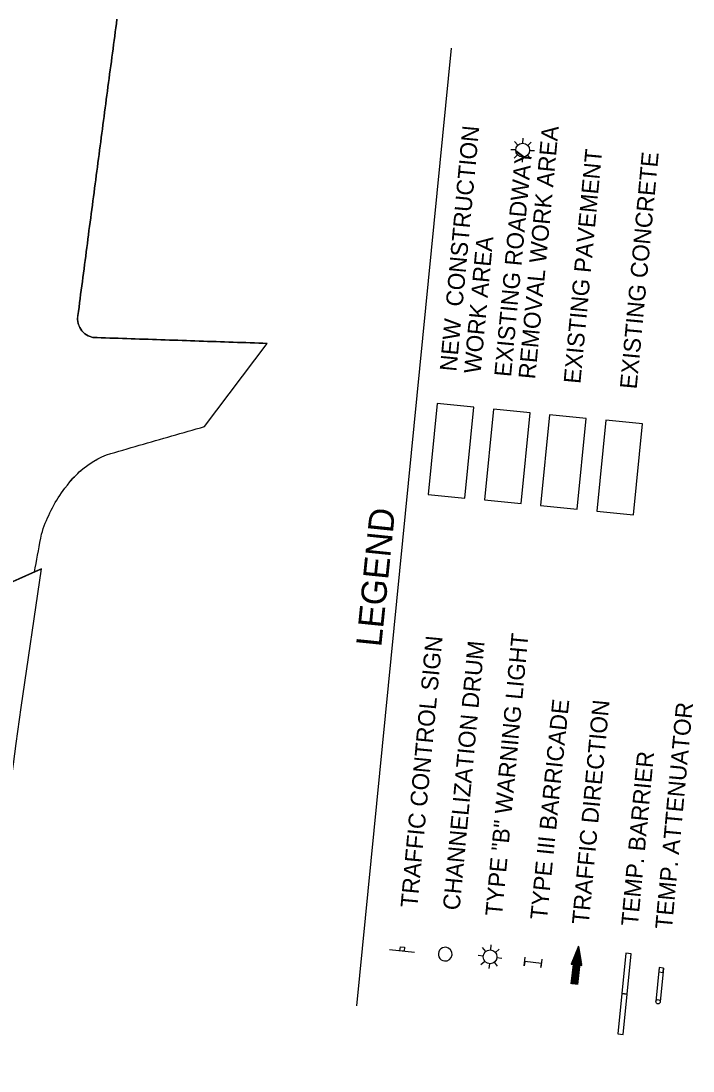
# Model space of a CAD drawing. Extents: x 1795987 to 1799700, y 243690 to 251545.
# Drawn here: x 1797662.2 to 1797973.5, y 245413.3 to 245899.5 of the extents above; entities that cross this region are included whole.
import ezdxf

# ---------------------------------------------------------------- set-up
doc = ezdxf.new("R2010")
doc.units = 0
for name, color, linetype in [('Level 23', 7, 'Continuous'), ('Level 31', 7, 'Continuous'), ('Level 4', 7, 'Continuous'), ('Prop_Horiz Alignment', 7, 'Continuous')]:
    doc.layers.add(name, color=color, linetype=linetype)

# ---------------------------------------------------------------- blocks, each defined once
blk = doc.blocks.new('T21LR')
at = {"layer": 'Level 23'}
for p, q in [((0, 2), (31.5, 2)), ((0, -2), (31.5, -2))]:
    blk.add_line(p, q, dxfattribs=at)
blk.add_lwpolyline([(0, -2), (4, -2), (4, 2), (0, 2)], close=True, dxfattribs=at)
blk.add_circle((31.5, 0), 2, dxfattribs=at)

msp = doc.modelspace()

# ---------------------------------------------------------------- linework, layer by layer
at = {"layer": 'Level 31'}
for p, q in [((1797817.74, 245443.45), (1797861.68, 245886.96)), ((1797877.46, 245468.63), (1797875.99, 245470.41)), ((1797879.8, 245469.34), (1797880.02, 245471.64)), ((1797920.43, 245471.1), (1797916.98, 245462.78)), ((1797921.95, 245462.22), (1797920.43, 245471.1)), ((1797844.52, 245468.23), (1797832.88, 245469.38)), ((1797876.3, 245466.47), (1797874, 245466.7)), ((1797883.74, 245469.65), (1797881.95, 245468.18)), ((1797882.66, 245465.84), (1797884.96, 245465.61)), ((1797875.22, 245462.67), (1797877.01, 245464.13)), ((1797879.17, 245462.98), (1797878.94, 245460.68)), ((1797882.97, 245461.9), (1797881.51, 245463.69)), ((1797917.92, 245462.67), (1797916.9, 245453.65)), ((1797916.98, 245462.78), (1797917.92, 245462.67)), ((1797920, 245453.3), (1797921.02, 245462.33)), ((1797921.02, 245462.33), (1797921.95, 245462.22))]:
    msp.add_line(p, q, dxfattribs=at)
for points in [[(1797867.8, 245678.59), (1797871.97, 245720.66), (1797854.98, 245722.34), (1797850.81, 245680.28)], [(1797893.84, 245676.01), (1797898, 245718.08), (1797881.02, 245719.76), (1797876.85, 245677.7)], [(1797919.87, 245673.43), (1797924.04, 245715.5), (1797907.05, 245717.18), (1797902.88, 245675.12)], [(1797945.91, 245670.85), (1797950.08, 245712.92), (1797933.09, 245714.61), (1797928.92, 245672.54)], [(1797837.73, 245468.9), (1797837.92, 245470.84), (1797839.86, 245470.65), (1797839.67, 245468.71)], [(1797944.86, 245467.59), (1797942.37, 245467.84), (1797940.52, 245449.18), (1797943.01, 245448.93)], [(1797943.01, 245448.93), (1797940.52, 245449.18), (1797938.68, 245430.52), (1797941.17, 245430.27)]]:
    msp.add_lwpolyline(points, close=True, dxfattribs=at)
for points in [[(1797920.3, 245470.77), (1797918.36, 245453.49)], [(1797920.53, 245470.52), (1797918.61, 245453.46)], [(1797903.5, 245465.04), (1797903.05, 245461.16), (1797903.28, 245463.1), (1797895.53, 245464), (1797895.3, 245462.06), (1797895.75, 245465.94)], [(1797918.5, 245466.45), (1797917.06, 245453.63)], [(1797918.86, 245467.32), (1797917.32, 245453.6)], [(1797919.22, 245468.18), (1797917.58, 245453.57)], [(1797918.15, 245465.59), (1797917.82, 245462.68)], [(1797919.58, 245469.05), (1797917.84, 245453.54)], [(1797919.94, 245469.91), (1797918.1, 245453.51)], [(1797920.69, 245469.6), (1797918.87, 245453.43)], [(1797920.85, 245468.68), (1797919.13, 245453.4)], [(1797921.01, 245467.75), (1797919.39, 245453.37)], [(1797921.16, 245466.83), (1797919.65, 245453.34)], [(1797921.32, 245465.91), (1797919.91, 245453.31)], [(1797917.07, 245463), (1797917.04, 245462.77)], [(1797917.43, 245463.86), (1797917.3, 245462.74)], [(1797917.79, 245464.72), (1797917.56, 245462.71)], [(1797921.48, 245464.99), (1797921.18, 245462.31)], [(1797921.64, 245464.06), (1797921.44, 245462.28)], [(1797921.8, 245463.14), (1797921.7, 245462.25)]]:
    msp.add_lwpolyline(points, dxfattribs=at)
msp.add_circle((1797879.48, 245466.16), 3.19, dxfattribs=at)
for start, end in [(84.3414, 264.3414), (264.3414, 84.3414)]:
    msp.add_arc((1797858.72, 245467.4), 3.18, start, end, dxfattribs=at)
at = {"layer": 'Level 4'}
for p, q in [((1797894.68, 245842.86), (1797894.75, 245845.17)), ((1797891.39, 245839.77), (1797889.08, 245839.84)), ((1797892.39, 245842), (1797890.81, 245843.68)), ((1797898.59, 245843.44), (1797896.91, 245841.86)), ((1797890.57, 245835.9), (1797892.25, 245837.48)), ((1797894.48, 245836.48), (1797894.41, 245834.17)), ((1797898.35, 245835.66), (1797896.77, 245837.34)), ((1797897.77, 245839.57), (1797900.08, 245839.5))]:
    msp.add_line(p, q, dxfattribs=at)
msp.add_circle((1797894.58, 245839.67), 3.19, dxfattribs=at)
at = {"layer": 'Prop_Horiz Alignment'}
for p, q in [((1797706.15, 245896.39), (1797706.41, 245898.35)), ((1797706.41, 245898.35), (1797706.67, 245900.31)), ((1797705.62, 245892.48), (1797705.88, 245894.44)), ((1797705.88, 245894.44), (1797706.15, 245896.39)), ((1797704.84, 245886.62), (1797705.1, 245888.57)), ((1797705.1, 245888.57), (1797705.36, 245890.53)), ((1797705.36, 245890.53), (1797705.62, 245892.48)), ((1797704.32, 245882.71), (1797704.58, 245884.66)), ((1797704.58, 245884.66), (1797704.84, 245886.62)), ((1797703.54, 245876.84), (1797703.8, 245878.8)), ((1797703.8, 245878.8), (1797704.06, 245880.75)), ((1797704.06, 245880.75), (1797704.32, 245882.71)), ((1797703.02, 245872.93), (1797703.28, 245874.88)), ((1797703.28, 245874.88), (1797703.54, 245876.84)), ((1797702.25, 245867.06), (1797702.5, 245869.02)), ((1797702.5, 245869.02), (1797702.76, 245870.97)), ((1797702.76, 245870.97), (1797703.02, 245872.93)), ((1797701.73, 245863.15), (1797701.99, 245865.11)), ((1797701.99, 245865.11), (1797702.25, 245867.06)), ((1797700.95, 245857.28), (1797701.21, 245859.24)), ((1797701.21, 245859.24), (1797701.47, 245861.19)), ((1797701.47, 245861.19), (1797701.73, 245863.15)), ((1797700.43, 245853.37), (1797700.69, 245855.33)), ((1797700.69, 245855.33), (1797700.95, 245857.28)), ((1797699.65, 245847.51), (1797699.91, 245849.46)), ((1797699.91, 245849.46), (1797700.17, 245851.42)), ((1797700.17, 245851.42), (1797700.43, 245853.37)), ((1797699.14, 245843.59), (1797699.4, 245845.55)), ((1797699.4, 245845.55), (1797699.65, 245847.51)), ((1797698.36, 245837.73), (1797698.62, 245839.68)), ((1797698.62, 245839.68), (1797698.88, 245841.64)), ((1797698.88, 245841.64), (1797699.14, 245843.59)), ((1797697.84, 245833.82), (1797698.1, 245835.77)), ((1797698.1, 245835.77), (1797698.36, 245837.73)), ((1797697.32, 245829.9), (1797697.58, 245831.86)), ((1797697.58, 245831.86), (1797697.84, 245833.82)), ((1797696.55, 245824.04), (1797696.8, 245825.99)), ((1797696.8, 245825.99), (1797697.06, 245827.95)), ((1797697.06, 245827.95), (1797697.32, 245829.9)), ((1797696.03, 245820.1), (1797696.29, 245822.07)), ((1797696.29, 245822.07), (1797696.55, 245824.04)), ((1797695.26, 245814.21), (1797695.52, 245816.17)), ((1797695.52, 245816.17), (1797695.77, 245818.14)), ((1797695.77, 245818.14), (1797696.03, 245820.1)), ((1797694.74, 245810.27), (1797695, 245812.24)), ((1797695, 245812.24), (1797695.26, 245814.21)), ((1797693.97, 245804.38), (1797694.23, 245806.34)), ((1797694.23, 245806.34), (1797694.49, 245808.31)), ((1797694.49, 245808.31), (1797694.74, 245810.27)), ((1797693.46, 245800.44), (1797693.71, 245802.41)), ((1797693.71, 245802.41), (1797693.97, 245804.38)), ((1797692.69, 245794.55), (1797692.94, 245796.51)), ((1797692.94, 245796.51), (1797693.2, 245798.48)), ((1797693.2, 245798.48), (1797693.46, 245800.44)), ((1797692.17, 245790.61), (1797692.43, 245792.58)), ((1797692.43, 245792.58), (1797692.69, 245794.55)), ((1797691.4, 245784.71), (1797691.66, 245786.68)), ((1797691.66, 245786.68), (1797691.91, 245788.65)), ((1797691.91, 245788.65), (1797692.17, 245790.61)), ((1797690.88, 245780.78), (1797691.14, 245782.75)), ((1797691.14, 245782.75), (1797691.4, 245784.71)), ((1797690.11, 245774.88), (1797690.37, 245776.85)), ((1797690.37, 245776.85), (1797690.63, 245778.82)), ((1797690.63, 245778.82), (1797690.88, 245780.78)), ((1797689.6, 245770.95), (1797689.85, 245772.92)), ((1797689.85, 245772.92), (1797690.11, 245774.88)), ((1797688.83, 245765.05), (1797689.08, 245767.02)), ((1797689.08, 245767.02), (1797689.34, 245768.99)), ((1797689.34, 245768.99), (1797689.6, 245770.95)), ((1797688.45, 245761.22), (1797688.57, 245763.09)), ((1797688.57, 245763.09), (1797688.83, 245765.05)), ((1797688.73, 245759.36), (1797688.45, 245761.22)), ((1797689.39, 245757.61), (1797688.73, 245759.36)), ((1797690.41, 245756.04), (1797689.39, 245757.61)), ((1797691.74, 245754.71), (1797690.41, 245756.04)), ((1797693.32, 245753.7), (1797691.74, 245754.71)), ((1797695.47, 245752.96), (1797693.32, 245753.7)), ((1797697.44, 245752.89), (1797695.47, 245752.96)), ((1797699.41, 245752.82), (1797697.44, 245752.89)), ((1797701.38, 245752.76), (1797699.41, 245752.82)), ((1797703.35, 245752.69), (1797701.38, 245752.76)), ((1797705.32, 245752.62), (1797703.35, 245752.69)), ((1797707.29, 245752.56), (1797705.32, 245752.62)), ((1797709.26, 245752.49), (1797707.29, 245752.56)), ((1797711.23, 245752.42), (1797709.26, 245752.49)), ((1797713.2, 245752.36), (1797711.23, 245752.42)), ((1797715.17, 245752.29), (1797713.2, 245752.36)), ((1797717.14, 245752.22), (1797715.17, 245752.29)), ((1797719.11, 245752.16), (1797717.14, 245752.22)), ((1797721.08, 245752.09), (1797719.11, 245752.16)), ((1797723.05, 245752.02), (1797721.08, 245752.09)), ((1797725.02, 245751.96), (1797723.05, 245752.02)), ((1797726.99, 245751.89), (1797725.02, 245751.96)), ((1797728.96, 245751.82), (1797726.99, 245751.89)), ((1797730.94, 245751.76), (1797728.96, 245751.82)), ((1797732.91, 245751.69), (1797730.94, 245751.76)), ((1797734.88, 245751.63), (1797732.91, 245751.69)), ((1797736.85, 245751.56), (1797734.88, 245751.63)), ((1797738.82, 245751.49), (1797736.85, 245751.56)), ((1797740.79, 245751.43), (1797738.82, 245751.49)), ((1797742.76, 245751.36), (1797740.79, 245751.43)), ((1797744.73, 245751.29), (1797742.76, 245751.36)), ((1797746.7, 245751.23), (1797744.73, 245751.29)), ((1797748.67, 245751.16), (1797746.7, 245751.23)), ((1797747.18, 245711.68), (1797776.25, 245750.23)), ((1797747.18, 245711.68), (1797776.25, 245750.23)), ((1797750.64, 245751.09), (1797748.67, 245751.16)), ((1797752.61, 245751.03), (1797750.64, 245751.09)), ((1797754.58, 245750.96), (1797752.61, 245751.03)), ((1797756.55, 245750.89), (1797754.58, 245750.96)), ((1797758.52, 245750.83), (1797756.55, 245750.89)), ((1797760.49, 245750.76), (1797758.52, 245750.83)), ((1797762.46, 245750.69), (1797760.49, 245750.76)), ((1797764.43, 245750.63), (1797762.46, 245750.69)), ((1797766.4, 245750.56), (1797764.43, 245750.63)), ((1797768.37, 245750.49), (1797766.4, 245750.56)), ((1797770.34, 245750.43), (1797768.37, 245750.49)), ((1797772.31, 245750.36), (1797770.34, 245750.43)), ((1797774.28, 245750.29), (1797772.31, 245750.36)), ((1797776.25, 245750.23), (1797774.28, 245750.29)), ((1797733.97, 245707.89), (1797735.86, 245708.43)), ((1797735.86, 245708.43), (1797737.75, 245708.97)), ((1797737.75, 245708.97), (1797739.63, 245709.52)), ((1797739.63, 245709.52), (1797741.52, 245710.06)), ((1797741.52, 245710.06), (1797743.41, 245710.6)), ((1797743.41, 245710.6), (1797745.3, 245711.14)), ((1797745.3, 245711.14), (1797747.18, 245711.68)), ((1797716.99, 245703.01), (1797718.88, 245703.55)), ((1797718.88, 245703.55), (1797720.76, 245704.1)), ((1797720.76, 245704.1), (1797722.65, 245704.64)), ((1797722.65, 245704.64), (1797724.54, 245705.18)), ((1797724.54, 245705.18), (1797726.43, 245705.72)), ((1797726.43, 245705.72), (1797728.31, 245706.26)), ((1797728.31, 245706.26), (1797730.2, 245706.81)), ((1797730.2, 245706.81), (1797732.09, 245707.35)), ((1797732.09, 245707.35), (1797733.97, 245707.89)), ((1797700.77, 245698.18), (1797701.89, 245698.68)), ((1797701.89, 245698.68), (1797703.78, 245699.22)), ((1797703.78, 245699.22), (1797705.67, 245699.76)), ((1797705.67, 245699.76), (1797707.56, 245700.3)), ((1797707.56, 245700.3), (1797709.44, 245700.84)), ((1797709.44, 245700.84), (1797711.33, 245701.39)), ((1797711.33, 245701.39), (1797713.22, 245701.93)), ((1797713.22, 245701.93), (1797715.1, 245702.47)), ((1797715.1, 245702.47), (1797716.99, 245703.01)), ((1797692.48, 245693.34), (1797694.19, 245694.55)), ((1797694.19, 245694.55), (1797695.96, 245695.68)), ((1797695.96, 245695.68), (1797697.79, 245696.72)), ((1797697.79, 245696.72), (1797699.66, 245697.68)), ((1797699.66, 245697.68), (1797700.77, 245698.18)), ((1797686.25, 245687.73), (1797687.71, 245689.24)), ((1797687.71, 245689.24), (1797689.23, 245690.68)), ((1797689.23, 245690.68), (1797690.82, 245692.05)), ((1797690.82, 245692.05), (1797692.48, 245693.34)), ((1797682.48, 245683.11), (1797683.68, 245684.63)), ((1797683.68, 245684.63), (1797684.87, 245686.15)), ((1797684.87, 245686.15), (1797686.25, 245687.73)), ((1797679.47, 245678.73), (1797680.2, 245679.84)), ((1797680.2, 245679.84), (1797680.93, 245680.95)), ((1797680.93, 245680.95), (1797681.71, 245682.03)), ((1797681.71, 245682.03), (1797682.48, 245683.11)), ((1797676.8, 245674.14), (1797677.45, 245675.3)), ((1797677.45, 245675.3), (1797678.09, 245676.46)), ((1797678.09, 245676.46), (1797678.78, 245677.6)), ((1797678.78, 245677.6), (1797679.47, 245678.73)), ((1797674.49, 245669.36), (1797675.04, 245670.57)), ((1797675.04, 245670.57), (1797675.6, 245671.77)), ((1797675.6, 245671.77), (1797676.2, 245672.96)), ((1797676.2, 245672.96), (1797676.8, 245674.14)), ((1797672.54, 245664.42), (1797673, 245665.66)), ((1797673, 245665.66), (1797673.47, 245666.91)), ((1797673.47, 245666.91), (1797673.98, 245668.13)), ((1797673.98, 245668.13), (1797674.49, 245669.36)), ((1797670.99, 245658.01), (1797671.35, 245659.95)), ((1797671.35, 245659.95), (1797671.7, 245661.9)), ((1797671.7, 245661.9), (1797672.12, 245663.16)), ((1797672.12, 245663.16), (1797672.54, 245664.42)), ((1797670.27, 245654.12), (1797670.63, 245656.06)), ((1797670.63, 245656.06), (1797670.99, 245658.01)), ((1797669.2, 245648.28), (1797669.56, 245650.23)), ((1797669.56, 245650.23), (1797669.92, 245652.17)), ((1797669.92, 245652.17), (1797670.27, 245654.12)), ((1797629.32, 245626.92), (1797671.67, 245645.81)), ((1797668.49, 245644.39), (1797668.85, 245646.34)), ((1797668.85, 245646.34), (1797669.2, 245648.28)), ((1797629.32, 245626.92), (1797668.49, 245644.39))]:
    msp.add_line(p, q, dxfattribs=at)
for points in [[(1797706.67, 245900.31), (1797706.41, 245898.35), (1797706.15, 245896.39), (1797705.88, 245894.44), (1797705.62, 245892.48), (1797705.36, 245890.53), (1797705.1, 245888.57), (1797704.84, 245886.62), (1797704.58, 245884.66), (1797704.32, 245882.71), (1797704.06, 245880.75), (1797703.8, 245878.8), (1797703.54, 245876.84), (1797703.28, 245874.88), (1797703.02, 245872.93), (1797702.76, 245870.97), (1797702.5, 245869.02), (1797702.25, 245867.06), (1797701.99, 245865.11), (1797701.73, 245863.15), (1797701.47, 245861.19), (1797701.21, 245859.24), (1797700.95, 245857.28), (1797700.69, 245855.33), (1797700.43, 245853.37), (1797700.17, 245851.42), (1797699.91, 245849.46), (1797699.65, 245847.51), (1797699.4, 245845.55), (1797699.14, 245843.59), (1797698.88, 245841.64), (1797698.62, 245839.68), (1797698.36, 245837.73), (1797698.1, 245835.77), (1797697.84, 245833.82), (1797697.58, 245831.86), (1797697.32, 245829.9), (1797697.06, 245827.95), (1797696.8, 245825.99), (1797696.55, 245824.04), (1797696.29, 245822.07), (1797696.03, 245820.1), (1797695.77, 245818.14), (1797695.52, 245816.17), (1797695.26, 245814.21), (1797695, 245812.24), (1797694.74, 245810.27), (1797694.49, 245808.31), (1797694.23, 245806.34), (1797693.97, 245804.38), (1797693.71, 245802.41), (1797693.46, 245800.44), (1797693.2, 245798.48), (1797692.94, 245796.51), (1797692.69, 245794.55), (1797692.43, 245792.58), (1797692.17, 245790.61), (1797691.91, 245788.65), (1797691.66, 245786.68), (1797691.4, 245784.71), (1797691.14, 245782.75), (1797690.88, 245780.78), (1797690.63, 245778.82), (1797690.37, 245776.85), (1797690.11, 245774.88), (1797689.85, 245772.92), (1797689.6, 245770.95), (1797689.34, 245768.99), (1797689.08, 245767.02), (1797688.83, 245765.05), (1797688.57, 245763.09)], [(1797688.57, 245763.09), (1797688.46, 245762.16), (1797688.45, 245761.22), (1797688.54, 245760.28), (1797688.73, 245759.36), (1797689.01, 245758.47), (1797689.39, 245757.61), (1797689.86, 245756.8), (1797690.41, 245756.04), (1797691.04, 245755.34), (1797691.74, 245754.71), (1797692.5, 245754.17), (1797693.32, 245753.7), (1797694.18, 245753.33), (1797695.47, 245752.96), (1797697.44, 245752.89), (1797699.41, 245752.82), (1797701.38, 245752.76), (1797703.35, 245752.69), (1797705.32, 245752.62), (1797707.29, 245752.56), (1797709.26, 245752.49), (1797711.23, 245752.42), (1797713.2, 245752.36), (1797715.17, 245752.29), (1797717.14, 245752.22), (1797719.11, 245752.16), (1797721.08, 245752.09), (1797723.05, 245752.02), (1797725.02, 245751.96), (1797726.99, 245751.89), (1797728.96, 245751.82), (1797730.94, 245751.76), (1797732.91, 245751.69), (1797734.88, 245751.63), (1797736.85, 245751.56), (1797738.82, 245751.49), (1797740.79, 245751.43), (1797742.76, 245751.36), (1797744.73, 245751.29), (1797746.7, 245751.23), (1797748.67, 245751.16), (1797750.64, 245751.09), (1797752.61, 245751.03), (1797754.58, 245750.96), (1797756.55, 245750.89), (1797758.52, 245750.83), (1797760.49, 245750.76), (1797762.46, 245750.69), (1797764.43, 245750.63), (1797766.4, 245750.56), (1797768.37, 245750.49), (1797770.34, 245750.43), (1797772.31, 245750.36), (1797774.28, 245750.29), (1797776.25, 245750.23)], [(1797902.88, 245675.12), (1797919.87, 245673.43), (1797924.04, 245715.5), (1797907.05, 245717.18), (1797902.88, 245675.12)], [(1797668.49, 245644.39), (1797668.85, 245646.34), (1797669.2, 245648.28), (1797669.56, 245650.23), (1797669.92, 245652.17), (1797670.27, 245654.12), (1797670.63, 245656.06), (1797670.99, 245658.01), (1797671.35, 245659.95), (1797671.7, 245661.9), (1797672.12, 245663.16), (1797672.54, 245664.42), (1797673, 245665.66), (1797673.47, 245666.91), (1797673.98, 245668.13), (1797674.49, 245669.36), (1797675.04, 245670.57), (1797675.6, 245671.77), (1797676.2, 245672.96), (1797676.8, 245674.14), (1797677.45, 245675.3), (1797678.09, 245676.46), (1797678.78, 245677.6), (1797679.47, 245678.73), (1797680.2, 245679.84), (1797680.93, 245680.95), (1797681.71, 245682.03), (1797682.48, 245683.11), (1797683.68, 245684.63), (1797684.87, 245686.15), (1797685.56, 245686.94), (1797686.25, 245687.73), (1797686.98, 245688.49), (1797687.71, 245689.24), (1797688.47, 245689.96), (1797689.23, 245690.68), (1797690.03, 245691.37), (1797690.82, 245692.05), (1797691.65, 245692.7), (1797692.48, 245693.34), (1797693.34, 245693.95), (1797694.19, 245694.55), (1797695.08, 245695.12), (1797695.96, 245695.68), (1797696.87, 245696.2), (1797697.79, 245696.72), (1797698.72, 245697.2), (1797699.66, 245697.68), (1797700.77, 245698.18), (1797701.89, 245698.68), (1797703.78, 245699.22), (1797705.67, 245699.76), (1797707.56, 245700.3), (1797709.44, 245700.84), (1797711.33, 245701.39), (1797713.22, 245701.93), (1797715.1, 245702.47), (1797716.99, 245703.01), (1797718.88, 245703.55), (1797720.76, 245704.1), (1797722.65, 245704.64), (1797724.54, 245705.18), (1797726.43, 245705.72), (1797728.31, 245706.26), (1797730.2, 245706.81), (1797732.09, 245707.35), (1797733.97, 245707.89), (1797735.86, 245708.43), (1797737.75, 245708.97), (1797739.63, 245709.52), (1797741.52, 245710.06), (1797743.41, 245710.6), (1797745.3, 245711.14), (1797747.18, 245711.68)], [(1797632.68, 245373.59), (1797640.38, 245427.53), (1797646.03, 245467.33), (1797650.06, 245494.55), (1797652.35, 245511.93), (1797658.75, 245555.41), (1797660.02, 245564.89), (1797662.33, 245581.55), (1797671.67, 245645.81), (1797668.49, 245644.39)], [(1797668.49, 245644.39), (1797629.32, 245626.92), (1797625.37, 245599.17), (1797622.91, 245582.88), (1797618.72, 245552.94), (1797616.82, 245538.81), (1797615.92, 245528.8), (1797612.79, 245512.8), (1797610.88, 245498.85), (1797608.73, 245484.63), (1797603.87, 245446.86), (1797600.33, 245424.56), (1797599.68, 245418.39), (1797596.56, 245399.07)]]:
    msp.add_lwpolyline(points, dxfattribs=at)

# ---------------------------------------------------------------- block references
at = {"layer": 'Level 31', "xscale": 0.5000000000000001, "yscale": 0.5000000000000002, "rotation": -95.50928026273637}
msp.add_blockref('T21LR', (1797958.84, 245461.05), dxfattribs=at)

# ---------------------------------------------------------------- texts
at = {"layer": 'Level 31'}
for s, height, rotation, p in [('NEW  CONSTRUCTION', 7.7999, 84.6544, (1797863.89, 245736.99)), ('REMOVAL WORK AREA', 7.7999, 84.6544, (1797900.36, 245733.44)), ('EXISTING ROADWAY', 7.7999, 84.6544, (1797889.17, 245734.48)), ('EXISTING PAVEMENT', 7.7999, 84.6544, (1797921.3, 245731.32)), ('EXISTING CONCRETE', 7.7999, 84.6544, (1797947.35, 245728.82)), ('WORK AREA', 7.8, 84.6544, (1797875.08, 245735.94)), ('LEGEND', 11.7, 84.1754, (1797829.06, 245609.39)), ('TYPE "B" WARNING LIGHT', 7.7999, 84.6544, (1797885.02, 245484.78)), ('TRAFFIC CONTROL SIGN', 7.7999, 84.6544, (1797845.77, 245488.67)), ('CHANNELIZATION DRUM', 7.7999, 84.6544, (1797865.33, 245487.48)), ('TYPE III BARRICADE', 7.7999, 84.1754, (1797905.8, 245483.02)), ('TRAFFIC DIRECTION', 7.7999, 84.6544, (1797925.16, 245480.94)), ('TEMP. ATTENUATOR', 7.7999, 84.6544, (1797963.7, 245478.67)), ('TEMP. BARRIER', 7.7999, 84.6544, (1797947.94, 245480.17))]:
    msp.add_text(s, height=height, rotation=rotation, dxfattribs=at).set_placement(p)

doc.saveas('drawing.dxf')
